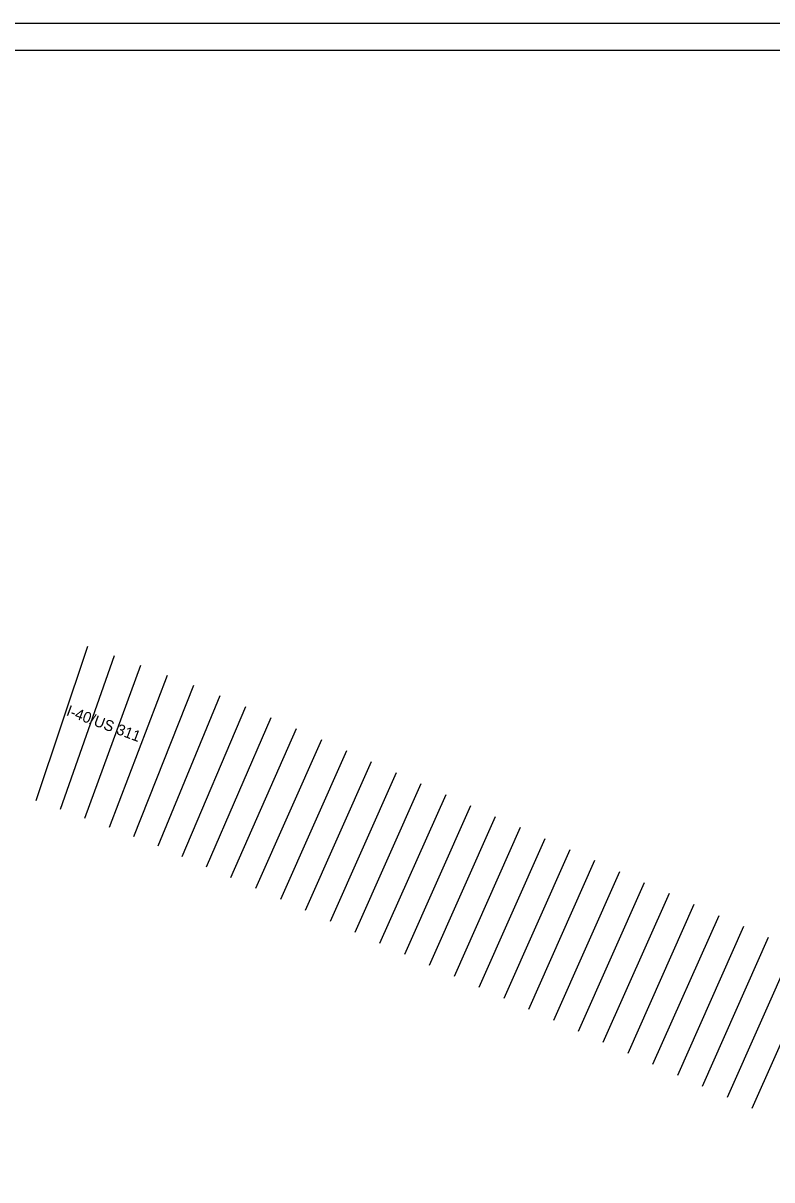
# Model space of a CAD drawing. Extents: x 1637454 to 1644154, y 841334 to 844734.
# Drawn here: x 1638403 to 1639782, y 842602 to 844734 of the extents above; entities that cross this region are included whole.
import ezdxf

# ---------------------------------------------------------------- set-up
doc = ezdxf.new("R2010")
doc.units = 0
for name, color, linetype in [('Exist Roads EOT Text', 7, 'Continuous'), ('Prop Shear Point Element on Plans', 7, 'Continuous'), ('Scratch_Level_1', 7, 'Continuous'), ('Sheet Plan And Profile CELL', 7, 'Continuous')]:
    doc.layers.add(name, color=color, linetype=linetype)

msp = doc.modelspace()

# ---------------------------------------------------------------- linework, layer by layer
at = {"layer": 'Prop Shear Point Element on Plans'}
for p, q in [((1638522.3, 843585.1), (1638426.8, 843300.8)), ((1638472.2, 843285.2), (1638571.5, 843568.3)), ((1638517.4, 843269), (1638620.4, 843550.7)), ((1638562.4, 843252.2), (1638669.1, 843532.6)), ((1638607.2, 843234.8), (1638717.6, 843513.8)), ((1638765.8, 843494.3), (1638651.7, 843216.9)), ((1638696.3, 843198.2), (1638813.5, 843474.4)), ((1638741, 843179), (1638860.6, 843454.1)), ((1638786.1, 843159.3), (1638907.1, 843433.8)), ((1638953.1, 843413.4), (1638831.5, 843139.2)), ((1638998.8, 843393.1), (1638877.2, 843118.9)), ((1639044.6, 843372.9), (1638923, 843098.6)), ((1639090.3, 843352.6), (1638968.7, 843078.4)), ((1639136, 843332.3), (1639014.4, 843058.1)), ((1639181.7, 843312.1), (1639060.1, 843037.8)), ((1639227.4, 843291.8), (1639105.8, 843017.6)), ((1639273.1, 843271.5), (1639151.5, 842997.3)), ((1639318.8, 843251.3), (1639197.2, 842977)), ((1639364.5, 843231), (1639242.9, 842956.8)), ((1639410.2, 843210.7), (1639288.6, 842936.5)), ((1639455.9, 843190.5), (1639334.3, 842916.2)), ((1639501.6, 843170.2), (1639380, 842896)), ((1639547.3, 843149.9), (1639425.7, 842875.7)), ((1639593.1, 843129.7), (1639471.4, 842855.4)), ((1639638.8, 843109.4), (1639517.2, 842835.2)), ((1639684.5, 843089.1), (1639562.9, 842814.9)), ((1639730.2, 843068.9), (1639608.6, 842794.6)), ((1639775.9, 843048.6), (1639654.3, 842774.3)), ((1639821.6, 843028.3), (1639700, 842754.1)), ((1639867.3, 843008.1), (1639745.7, 842733.8))]:
    msp.add_line(p, q, dxfattribs=at)
at = {"layer": 'Scratch_Level_1'}
msp.add_lwpolyline([(1637454.2, 841333.9), (1637454.2, 844733.9), (1644154.2, 844733.9), (1644154.2, 841333.9)], close=True, dxfattribs=at)
at = {"layer": 'Sheet Plan And Profile CELL'}
msp.add_lwpolyline([(1637504.2, 841383.9), (1637504.2, 844683.9), (1644104.2, 844683.9), (1644104.2, 841383.9)], close=True, dxfattribs=at)

# ---------------------------------------------------------------- texts
at = {"layer": 'Exist Roads EOT Text'}
msp.add_text('I-40/US 311', height=20, rotation=339.5451, dxfattribs=at).set_placement((1638481.6, 843458.8))

doc.saveas('drawing.dxf')
